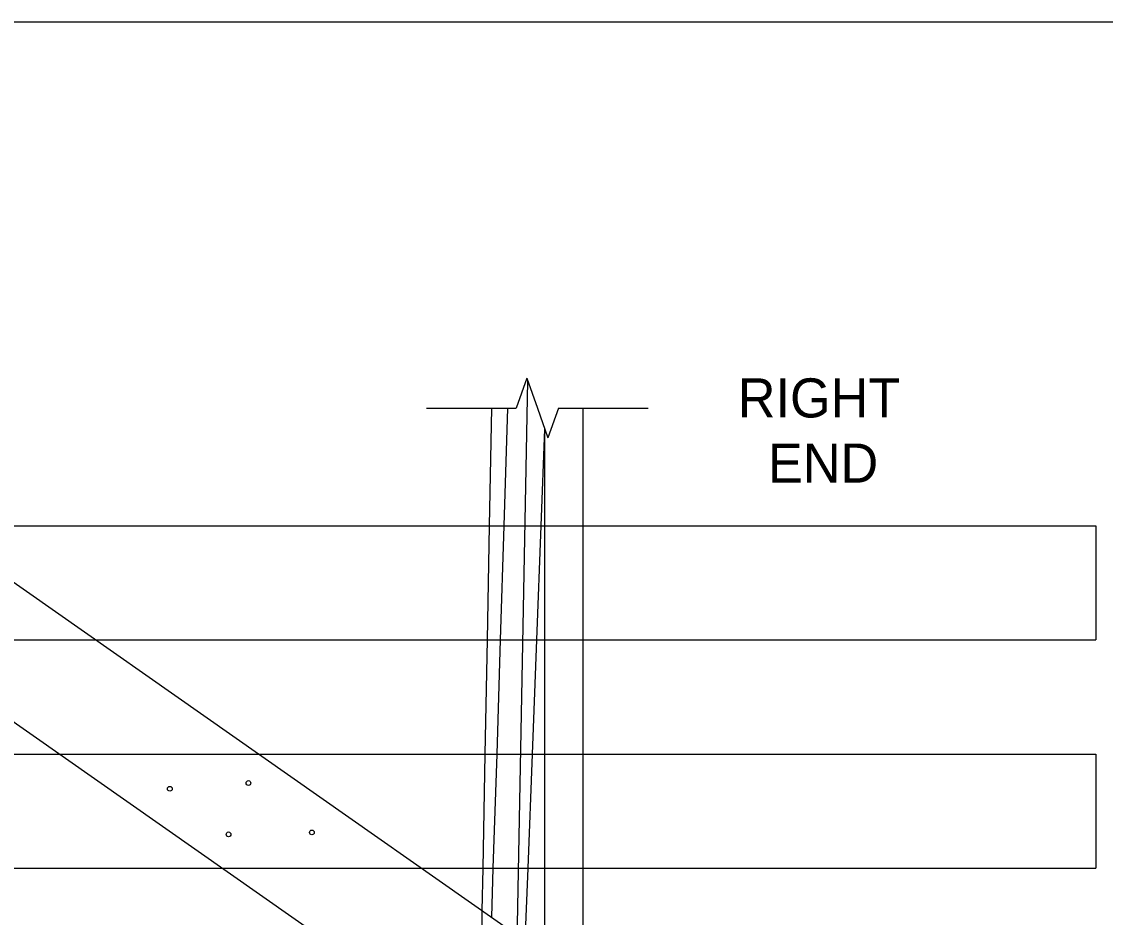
# Model space of a CAD drawing. Extents: x 49991.4 to 50021, y 49987.6 to 50011.4.
# Drawn here: x 50013.133 to 50014.797, y 49997.625 to 49998.999 of the extents above; entities that cross this region are included whole.
import ezdxf

# ---------------------------------------------------------------- set-up
doc = ezdxf.new("R2010")
doc.units = 0
for name, color, linetype in [('Level 1', 7, 'Continuous'), ('Level 2', 7, 'Continuous'), ('Level 4', 7, 'Continuous'), ('Level 6', 7, 'Continuous')]:
    doc.layers.add(name, color=color, linetype=linetype)

msp = doc.modelspace()

# ---------------------------------------------------------------- linework, layer by layer
at = {"layer": 'Level 1'}
for p, q in [((50012.4332, 49998.4062), (50014.4334, 49997.0056)), ((50014.5338, 49997.149), (50012.7383, 49998.4062)), ((50013.8515, 49998.2253), (50013.855, 49998.4062)), ((50013.8793, 49998.4062), (50013.8736, 49998.2253)), ((50013.995, 49998.4062), (50013.995, 49998.2253)), ((50013.9311, 49998.2253), (50013.9365, 49998.3738)), ((50013.9366, 49998.2253), (50013.9366, 49998.3735)), ((50012.9967, 49998.2253), (50014.7825, 49998.2253)), ((50014.7825, 49998.2253), (50014.7825, 49998.0503)), ((50013.2466, 49998.0503), (50014.7825, 49998.0503)), ((50013.8451, 49997.8753), (50013.8483, 49998.0503)), ((50013.8681, 49998.0503), (50013.8626, 49997.8753)), ((50013.9177, 49997.8753), (50013.9244, 49998.0503)), ((50013.9366, 49997.8753), (50013.9366, 49998.0503)), ((50013.995, 49998.0503), (50013.995, 49997.8753)), ((50009.1825, 49997.8753), (50013.1914, 49997.8753)), ((50013.4965, 49997.8753), (50014.7825, 49997.8753)), ((50014.7825, 49997.8753), (50014.7825, 49997.7003)), ((50009.1825, 49997.7003), (50013.4413, 49997.7003)), ((50013.7464, 49997.7003), (50014.7825, 49997.7003)), ((50013.8404, 49997.6345), (50013.8416, 49997.7003)), ((50013.8567, 49997.7003), (50013.8544, 49997.6247)), ((50013.9064, 49997.5883), (50013.9107, 49997.7003)), ((50013.9366, 49997.5672), (50013.9366, 49997.7003)), ((50013.995, 49997.7003), (50013.995, 49997.5263))]:
    msp.add_line(p, q, dxfattribs=at)
msp.add_lwpolyline([(49999.3835, 49998.9992), (50016.7501, 49998.9992), (50016.7501, 49987.7988), (49999.3835, 49987.7988)], close=True, dxfattribs=at)
for centre in [(50013.4814, 49997.8308), (50013.3607, 49997.822), (50013.4509, 49997.752), (50013.5789, 49997.755)]:
    msp.add_circle(centre, 0.00367, dxfattribs=at)
at = {"layer": 'Level 4'}
for p, q in [((50013.9101, 49998.4482), (50013.878, 49996.7649)), ((50013.8483, 49998.0503), (50013.8515, 49998.2253)), ((50013.8736, 49998.2253), (50013.8681, 49998.0503)), ((50013.9244, 49998.0503), (50013.9311, 49998.2253)), ((50013.9366, 49998.0503), (50013.9366, 49998.2253)), ((50013.995, 49998.2253), (50013.995, 49998.0503)), ((50012.9415, 49998.0503), (50013.2466, 49998.0503)), ((50013.1914, 49997.8753), (50013.4965, 49997.8753)), ((50013.8416, 49997.7003), (50013.8451, 49997.8753)), ((50013.8626, 49997.8753), (50013.8567, 49997.7003)), ((50013.9107, 49997.7003), (50013.9177, 49997.8753)), ((50013.9366, 49997.7003), (50013.9366, 49997.8753)), ((50013.995, 49997.8753), (50013.995, 49997.7003)), ((50013.4413, 49997.7003), (50013.7464, 49997.7003)), ((50013.8351, 49997.3503), (50013.8404, 49997.6345))]:
    msp.add_line(p, q, dxfattribs=at)
at = {"layer": 'Level 6'}
for p, q in [((50013.9088, 49998.4519), (50013.8926, 49998.4062)), ((50013.9088, 49998.4519), (50013.925, 49998.4062)), ((50013.755, 49998.4062), (50013.8926, 49998.4062)), ((50013.925, 49998.4062), (50013.9412, 49998.3605)), ((50013.9574, 49998.4062), (50013.9412, 49998.3605)), ((50013.9574, 49998.4062), (50014.095, 49998.4062))]:
    msp.add_line(p, q, dxfattribs=at)

# ---------------------------------------------------------------- texts
at = {"layer": 'Level 2'}
for s, p in [('RIGHT', (50014.2327, 49998.3918)), ('END', (50014.279, 49998.2918))]:
    msp.add_text(s, height=0.06, dxfattribs=at).set_placement(p)

doc.saveas('drawing.dxf')
